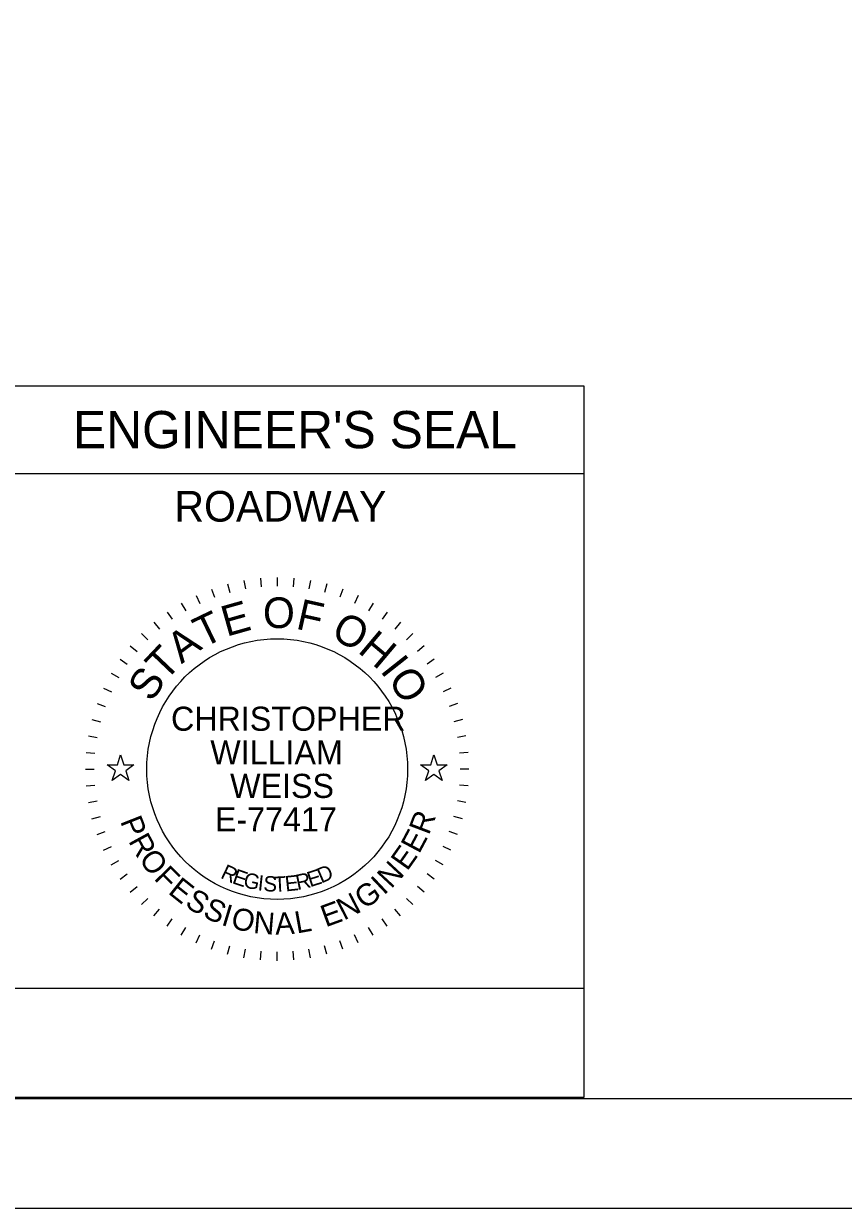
# Model space of a CAD drawing. Extents: x 0 to 34, y 0 to 22.
# Drawn here: x 22.34 to 26.08, y 0 to 5.41 of the extents above; entities that cross this region are included whole.
import ezdxf

# ---------------------------------------------------------------- set-up
doc = ezdxf.new("R2010")
doc.units = 0
for name, color, linetype in [('Default', 7, 'Continuous'), ('SH_Border', 7, 'Continuous'), ('SH_Cut_Line', 7, 'Continuous'), ('SH_Data', 7, 'Continuous')]:
    doc.layers.add(name, color=color, linetype=linetype)

msp = doc.modelspace()

# ---------------------------------------------------------------- linework, layer by layer
at = {"layer": 'Default'}
for points in [[(22.7212, 2.0254), (22.7681, 2.0254), (22.7826, 2.07), (22.7971, 2.0254), (22.844, 2.0254), (22.8061, 1.9978), (22.8206, 1.9532), (22.7826, 1.9808), (22.7446, 1.9532), (22.7591, 1.9978)], [(24.1512, 2.0254), (24.1981, 2.0254), (24.2126, 2.07), (24.2271, 2.0254), (24.274, 2.0254), (24.2361, 1.9978), (24.2506, 1.9532), (24.2126, 1.9808), (24.1746, 1.9532), (24.1891, 1.9978)]]:
    msp.add_lwpolyline(points, close=True, dxfattribs=at)
at = {"layer": 'SH_Border'}
msp.add_lwpolyline([(1.5, 21.5), (33.5, 21.5), (33.5, 0.5), (1.5, 0.5)], close=True, dxfattribs=at)
at = {"layer": 'SH_Cut_Line'}
msp.add_lwpolyline([(0, 0), (34, 0), (34, 22), (0, 22)], close=True, dxfattribs=at)
at = {"layer": 'SH_Data'}
for p, q in [((22.0976, 3.7554), (24.8976, 3.7554)), ((24.8976, 3.7554), (24.8976, 0.5054)), ((22.0976, 3.3554), (24.8976, 3.3554)), ((23.3457, 2.8672), (23.3526, 2.8278)), ((23.4214, 2.8771), (23.4248, 2.8373)), ((23.4976, 2.8804), (23.4976, 2.8404)), ((23.5739, 2.8771), (23.5704, 2.8373)), ((23.6496, 2.8672), (23.6426, 2.8278)), ((23.1984, 2.8277), (23.212, 2.7901)), ((23.2712, 2.8506), (23.2815, 2.812)), ((23.7241, 2.8506), (23.7137, 2.812)), ((23.7969, 2.8277), (23.7832, 2.7901)), ((23.0601, 2.7632), (23.0801, 2.7286)), ((23.1278, 2.7985), (23.1447, 2.7622)), ((23.8674, 2.7985), (23.8505, 2.7622)), ((23.9351, 2.7632), (23.9151, 2.7286)), ((22.9957, 2.7222), (23.0187, 2.6894)), ((23.9995, 2.7222), (23.9766, 2.6894)), ((22.9352, 2.6757), (22.9609, 2.6451)), ((24.0601, 2.6757), (24.0343, 2.6451)), ((22.8789, 2.6242), (22.9072, 2.5959)), ((24.1163, 2.6242), (24.0881, 2.5959)), ((22.8273, 2.5679), (22.858, 2.5422)), ((24.1679, 2.5679), (24.1373, 2.5422)), ((22.7809, 2.5073), (22.8136, 2.4844)), ((24.2144, 2.5073), (24.1816, 2.4844)), ((22.7398, 2.4429), (22.7745, 2.4229)), ((24.2554, 2.4429), (24.2208, 2.4229)), ((22.7046, 2.3752), (22.7409, 2.3583)), ((24.2906, 2.3752), (24.2544, 2.3583)), ((22.6754, 2.3047), (22.713, 2.291)), ((24.3199, 2.3047), (24.2823, 2.291)), ((22.6524, 2.2319), (22.6911, 2.2216)), ((24.3428, 2.2319), (24.3042, 2.2216)), ((22.6359, 2.1574), (22.6753, 2.1504)), ((24.3593, 2.1574), (24.3199, 2.1504)), ((22.626, 2.0817), (22.6658, 2.0782)), ((24.3693, 2.0817), (24.3294, 2.0782)), ((22.6226, 2.0054), (22.6626, 2.0054)), ((24.3726, 2.0054), (24.3326, 2.0054)), ((22.626, 1.9292), (22.6658, 1.9327)), ((24.3693, 1.9292), (24.3294, 1.9327)), ((22.6359, 1.8535), (22.6753, 1.8605)), ((24.3593, 1.8535), (24.3199, 1.8605)), ((22.6524, 1.779), (22.6911, 1.7893)), ((24.3428, 1.779), (24.3042, 1.7893)), ((22.6754, 1.7062), (22.713, 1.7199)), ((24.3199, 1.7062), (24.2823, 1.7199)), ((22.7046, 1.6357), (22.7409, 1.6526)), ((24.2906, 1.6357), (24.2544, 1.6526)), ((22.7398, 1.5679), (22.7745, 1.5879)), ((24.2554, 1.5679), (24.2208, 1.5879)), ((22.7809, 1.5036), (22.8136, 1.5265)), ((24.2144, 1.5036), (24.1816, 1.5265)), ((22.8273, 1.443), (22.858, 1.4687)), ((24.1679, 1.443), (24.1373, 1.4687)), ((22.8789, 1.3867), (22.9072, 1.415)), ((24.1163, 1.3867), (24.0881, 1.415)), ((22.9352, 1.3352), (22.9609, 1.3658)), ((24.0601, 1.3352), (24.0343, 1.3658)), ((22.9957, 1.2887), (23.0187, 1.3215)), ((23.9995, 1.2887), (23.9766, 1.3215)), ((23.0601, 1.2477), (23.0801, 1.2823)), ((23.1278, 1.2124), (23.1447, 1.2487)), ((23.8674, 1.2124), (23.8505, 1.2487)), ((23.9351, 1.2477), (23.9151, 1.2823)), ((23.1984, 1.1832), (23.212, 1.2208)), ((23.2712, 1.1603), (23.2815, 1.1989)), ((23.7241, 1.1603), (23.7137, 1.1989)), ((23.7969, 1.1832), (23.7832, 1.2208)), ((23.3457, 1.1437), (23.3526, 1.1831)), ((23.4214, 1.1338), (23.4248, 1.1736)), ((23.4976, 1.1304), (23.4976, 1.1704)), ((23.5739, 1.1338), (23.5704, 1.1736)), ((23.6496, 1.1437), (23.6426, 1.1831)), ((22.0976, 0.5054), (24.8976, 0.5054))]:
    msp.add_line(p, q, dxfattribs=at)
msp.add_lwpolyline([(22.0976, 0.5054), (22.0976, 1.0054), (24.8976, 1.0054), (24.8976, 0.5054)], close=True, dxfattribs=at)
msp.add_circle((23.4976, 2.0054), 0.595, dxfattribs=at)

# ---------------------------------------------------------------- texts
for s, height, p in [("ENGINEER'S SEAL", 0.17, (22.5652, 3.4704)), ('ROADWAY', 0.14, (23.0287, 3.1354)), ('CHRISTOPHER', 0.11, (23.0131, 2.1804)), ('WILLIAM', 0.11, (23.1923, 2.0271)), ('WEISS', 0.11, (23.2828, 1.8738)), ('E-77417', 0.11, (23.2135, 1.7205))]:
    msp.add_text(s, height=height, dxfattribs=at).set_placement(p)
for s, height, rotation, p in [('E', 0.14, 15.7571, (23.266, 2.6092)), ('O', 0.14, 359.7812, (23.4323, 2.6497)), ('F', 0.14, 347.4362, (23.5787, 2.6472)), ('T', 0.14, 25.7167, (23.1593, 2.5573)), ('O', 0.14, 332.2586, (23.7374, 2.607)), ('A', 0.14, 36.4747, (23.061, 2.4836)), ('H', 0.14, 319.9136, (23.8608, 2.5415)), ('T', 0.14, 46.4344, (22.9859, 2.4019)), ('I', 0.14, 308.367, (23.9641, 2.4538)), ('S', 0.14, 57.1924, (22.9257, 2.3069)), ('O', 0.14, 303.1491, (23.9998, 2.4143)), ('P', 0.1, 291.494, (22.7799, 1.7675)), ('R', 0.1, 69.2322, (24.1896, 1.7008)), ('E', 0.1, 61.9951, (24.1453, 1.6153)), ('R', 0.1, 298.7311, (22.8166, 1.6771)), ('O', 0.1, 306.4666, (22.8631, 1.5937)), ('E', 0.1, 54.758, (24.091, 1.5368)), ('R', 0.07, 334.487, (23.2351, 1.5105)), ('N', 0.1, 47.0224, (24.0178, 1.4562)), ('F', 0.1, 314.7068, (22.9319, 1.5037)), ('E', 0.07, 341.04, (23.2883, 1.4855)), ('G', 0.07, 347.4752, (23.3391, 1.4673)), ('I', 0.07, 353.7858, (23.4067, 1.4523)), ('S', 0.07, 356.8926, (23.4334, 1.4483)), ('T', 0.07, 3.0061, (23.4833, 1.4441)), ('E', 0.07, 6.0117, (23.5366, 1.4467)), ('R', 0.07, 11.9184, (23.5901, 1.4528)), ('E', 0.07, 17.6836, (23.6474, 1.4656)), ('D', 0.07, 23.3052, (23.6986, 1.4825)), ('I', 0.1, 43.287, (23.9845, 1.4268)), ('E', 0.1, 321.4393, (22.9954, 1.4402)), ('G', 0.1, 35.0469, (23.8957, 1.3624)), ('S', 0.1, 328.6764, (23.0719, 1.3807)), ('S', 0.1, 335.9134, (23.154, 1.332)), ('N', 0.1, 27.3113, (23.8021, 1.313)), ('I', 0.1, 343.1505, (23.2383, 1.2951)), ('O', 0.1, 346.8859, (23.2815, 1.2806)), ('N', 0.1, 355.1261, (23.3864, 1.2572)), ('L', 0.1, 10.0987, (23.587, 1.2545)), ('E', 0.1, 20.0742, (23.7188, 1.2825)), ('A', 0.1, 2.8617, (23.4899, 1.2491))]:
    msp.add_text(s, height=height, rotation=rotation, dxfattribs=at).set_placement(p)

doc.saveas('drawing.dxf')
